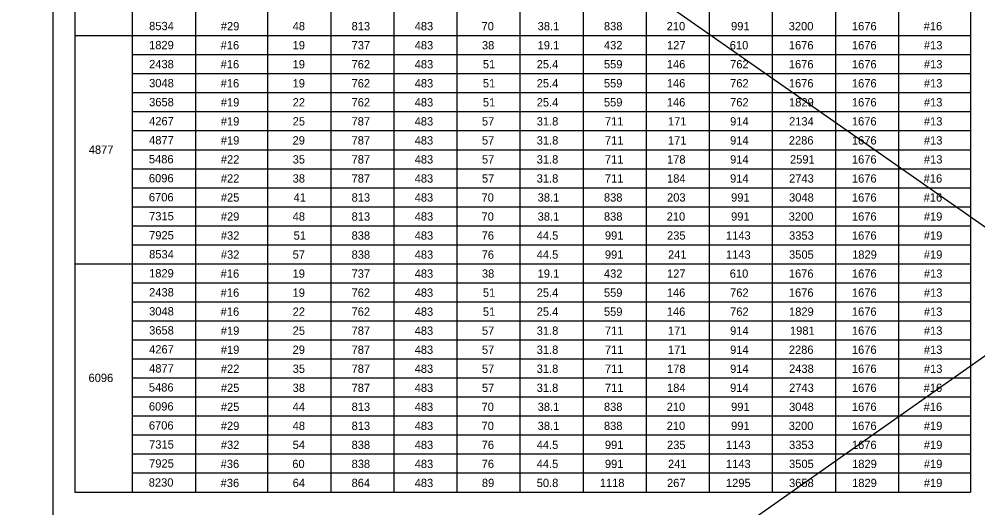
# Model space of a CAD drawing. Extents: x 3351 to 8430, y -3586 to 1457.
# Drawn here: x 7152.8 to 7507.3, y -991.4 to -810.5 of the extents above; entities that cross this region are included whole.
import ezdxf

# ---------------------------------------------------------------- set-up
doc = ezdxf.new("R2010")
doc.units = 0
doc.layers.add('1', color=7, linetype='Continuous')
doc.layers.add('2', color=7, linetype='Continuous')

msp = doc.modelspace()

# ---------------------------------------------------------------- linework, layer by layer
at = {"layer": '1'}
for p, q in [((7152.8, -637.24), (7925.95, -1178.57)), ((7927.1, -641.21), (7154.13, -1185.98)), ((7173.34, -639.31), (7173.34, -985.5)), ((7504.68, -639.31), (7504.68, -985.5)), ((7244.68, -703.31), (7244.68, -985.5)), ((7338.01, -703.31), (7338.01, -985.5)), ((7408.01, -703.31), (7408.01, -985.5)), ((7194.68, -985.5), (7194.68, -711.31)), ((7218.01, -711.31), (7218.01, -985.5)), ((7268.01, -711.31), (7268.01, -985.5)), ((7291.34, -711.31), (7291.34, -985.5)), ((7314.68, -711.31), (7314.68, -985.5)), ((7361.34, -711.31), (7361.34, -985.5)), ((7384.68, -711.31), (7384.68, -985.5)), ((7431.34, -711.31), (7431.34, -985.5)), ((7454.68, -711.31), (7454.68, -985.5)), ((7478.01, -711.31), (7478.01, -985.5)), ((7173.34, -816.54), (7504.68, -816.54)), ((7173.34, -816.54), (7504.68, -816.54)), ((7194.68, -823.58), (7504.68, -823.58)), ((7194.68, -830.62), (7504.68, -830.62)), ((7194.68, -837.66), (7504.68, -837.66)), ((7194.68, -844.7), (7504.68, -844.7)), ((7194.68, -851.74), (7504.68, -851.74)), ((7194.68, -858.78), (7504.68, -858.78)), ((7194.68, -865.82), (7504.68, -865.82)), ((7194.68, -872.86), (7504.68, -872.86)), ((7194.68, -879.9), (7504.68, -879.9)), ((7194.68, -886.94), (7504.68, -886.94)), ((7194.68, -893.98), (7504.68, -893.98)), ((7173.34, -901.02), (7504.68, -901.02)), ((7194.68, -908.06), (7504.68, -908.06)), ((7194.68, -915.1), (7504.68, -915.1)), ((7194.68, -922.14), (7504.68, -922.14)), ((7194.68, -929.18), (7504.68, -929.18)), ((7194.68, -936.22), (7504.68, -936.22)), ((7194.68, -943.26), (7504.68, -943.26)), ((7194.68, -950.3), (7504.68, -950.3)), ((7194.68, -957.34), (7504.68, -957.34)), ((7194.68, -964.38), (7504.68, -964.38)), ((7194.68, -971.42), (7504.68, -971.42)), ((7194.68, -978.46), (7504.68, -978.46)), ((7173.34, -985.5), (7504.68, -985.5))]:
    msp.add_line(p, q, dxfattribs=at)
at = {"layer": '2'}
msp.add_line((7165.34, -1195.31), (7165.34, -631.31), dxfattribs=at)

# ---------------------------------------------------------------- texts
at = {"layer": '1'}
for s, p in [('8534', (7200.86, -814.55)), ('#29', (7227.38, -814.6)), ('48', (7253.94, -814.6)), ('813', (7275.73, -814.6)), ('483', (7299.07, -814.6)), ('70', (7323.8, -814.6)), ('38.1', (7344.55, -814.6)), ('838', (7369.07, -814.6)), ('210', (7392.27, -814.6)), ('991', (7416.09, -814.6)), ('3200', (7437.4, -814.6)), ('1676', (7460.78, -814.6)), ('#16', (7487.31, -814.6)), ('1829', (7200.84, -821.59)), ('#16', (7227.31, -821.65)), ('19', (7253.92, -821.65)), ('737', (7275.73, -821.65)), ('483', (7299.07, -821.65)), ('38', (7323.94, -821.65)), ('19.1', (7344.55, -821.65)), ('432', (7369.07, -821.65)), ('127', (7392.4, -821.65)), ('610', (7415.6, -821.65)), ('1676', (7437.45, -821.65)), ('1676', (7460.78, -821.65)), ('#13', (7487.39, -821.65)), ('2438', (7200.86, -828.63)), ('#16', (7227.31, -828.69)), ('19', (7253.92, -828.69)), ('762', (7275.73, -828.69)), ('483', (7299.07, -828.69)), ('51', (7324.29, -828.69)), ('25.4', (7344.2, -828.69)), ('559', (7369.06, -828.69)), ('146', (7392.32, -828.69)), ('762', (7415.73, -828.69)), ('1676', (7437.45, -828.69)), ('1676', (7460.78, -828.69)), ('#13', (7487.39, -828.69)), ('3048', (7200.86, -835.67)), ('#16', (7227.31, -835.74)), ('19', (7253.92, -835.74)), ('762', (7275.73, -835.74)), ('483', (7299.07, -835.74)), ('51', (7324.29, -835.74)), ('25.4', (7344.2, -835.74)), ('559', (7369.06, -835.74)), ('146', (7392.32, -835.74)), ('762', (7415.73, -835.74)), ('1676', (7437.45, -835.74)), ('1676', (7460.78, -835.74)), ('#13', (7487.39, -835.74)), ('3658', (7200.86, -842.71)), ('#19', (7227.38, -842.78)), ('22', (7253.94, -842.78)), ('762', (7275.73, -842.78)), ('483', (7299.07, -842.78)), ('51', (7324.29, -842.78)), ('25.4', (7344.2, -842.78)), ('559', (7369.06, -842.78)), ('146', (7392.32, -842.78)), ('762', (7415.73, -842.78)), ('1829', (7437.52, -842.78)), ('1676', (7460.78, -842.78)), ('#13', (7487.39, -842.78)), ('4267', (7200.86, -849.75)), ('#19', (7227.38, -849.83)), ('25', (7253.94, -849.83)), ('787', (7275.73, -849.83)), ('483', (7299.07, -849.83)), ('57', (7323.94, -849.83)), ('31.8', (7344.2, -849.83)), ('711', (7369.42, -849.83)), ('171', (7392.75, -849.83)), ('914', (7415.73, -849.83)), ('2134', (7437.53, -849.83)), ('1676', (7460.78, -849.83)), ('#13', (7487.39, -849.83)), ('4877', (7200.86, -856.79)), ('#19', (7227.38, -856.87)), ('29', (7253.92, -856.87)), ('787', (7275.73, -856.87)), ('483', (7299.07, -856.87)), ('57', (7323.94, -856.87)), ('31.8', (7344.2, -856.87)), ('711', (7369.42, -856.87)), ('171', (7392.75, -856.87)), ('914', (7415.73, -856.87)), ('2286', (7437.45, -856.87)), ('1676', (7460.78, -856.87)), ('#13', (7487.39, -856.87)), ('4877', (7178.53, -860.31)), ('5486', (7200.77, -863.83)), ('#22', (7227.39, -863.91)), ('35', (7253.94, -863.91)), ('787', (7275.73, -863.91)), ('483', (7299.07, -863.91)), ('57', (7323.94, -863.91)), ('31.8', (7344.2, -863.91)), ('711', (7369.42, -863.91)), ('178', (7392.4, -863.91)), ('914', (7415.73, -863.91)), ('2591', (7437.88, -863.91)), ('1676', (7460.78, -863.91)), ('#13', (7487.39, -863.91)), ('6096', (7200.77, -870.87)), ('#22', (7227.39, -870.96)), ('38', (7253.94, -870.96)), ('787', (7275.73, -870.96)), ('483', (7299.07, -870.96)), ('57', (7323.94, -870.96)), ('31.8', (7344.2, -870.96)), ('711', (7369.42, -870.96)), ('184', (7392.4, -870.96)), ('914', (7415.73, -870.96)), ('2743', (7437.53, -870.96)), ('1676', (7460.78, -870.96)), ('#16', (7487.31, -870.96)), ('6706', (7200.77, -877.91)), ('#25', (7227.39, -878)), ('41', (7254.29, -878)), ('813', (7275.73, -878)), ('483', (7299.07, -878)), ('70', (7323.8, -878)), ('38.1', (7344.55, -878)), ('838', (7369.07, -878)), ('203', (7392.4, -878)), ('991', (7416.09, -878)), ('3048', (7437.53, -878)), ('1676', (7460.78, -878)), ('#16', (7487.31, -878)), ('7315', (7200.86, -884.95)), ('#29', (7227.38, -885.05)), ('48', (7253.94, -885.05)), ('813', (7275.73, -885.05)), ('483', (7299.07, -885.05)), ('70', (7323.8, -885.05)), ('38.1', (7344.55, -885.05)), ('838', (7369.07, -885.05)), ('210', (7392.27, -885.05)), ('991', (7416.09, -885.05)), ('3200', (7437.4, -885.05)), ('1676', (7460.78, -885.05)), ('#19', (7487.38, -885.05)), ('7925', (7200.86, -891.99)), ('#32', (7227.39, -892.09)), ('51', (7254.29, -892.09)), ('838', (7275.73, -892.09)), ('483', (7299.07, -892.09)), ('76', (7323.85, -892.09)), ('44.5', (7344.2, -892.09)), ('991', (7369.42, -892.09)), ('235', (7392.4, -892.09)), ('1143', (7414.2, -892.09)), ('3353', (7437.53, -892.09)), ('1676', (7460.78, -892.09)), ('#19', (7487.38, -892.09)), ('8534', (7200.86, -899.03)), ('#32', (7227.39, -899.14)), ('57', (7253.94, -899.14)), ('838', (7275.73, -899.14)), ('483', (7299.07, -899.14)), ('76', (7323.85, -899.14)), ('44.5', (7344.2, -899.14)), ('991', (7369.42, -899.14)), ('241', (7392.75, -899.14)), ('1143', (7414.2, -899.14)), ('3505', (7437.53, -899.14)), ('1829', (7460.85, -899.14)), ('#19', (7487.38, -899.14)), ('1829', (7200.84, -906.07)), ('#16', (7227.31, -906.18)), ('19', (7253.92, -906.18)), ('737', (7275.73, -906.18)), ('483', (7299.07, -906.18)), ('38', (7323.94, -906.18)), ('19.1', (7344.55, -906.18)), ('432', (7369.07, -906.18)), ('127', (7392.4, -906.18)), ('610', (7415.6, -906.18)), ('1676', (7437.45, -906.18)), ('1676', (7460.78, -906.18)), ('#13', (7487.39, -906.18)), ('2438', (7200.86, -913.11)), ('#16', (7227.31, -913.23)), ('19', (7253.92, -913.23)), ('762', (7275.73, -913.23)), ('483', (7299.07, -913.23)), ('51', (7324.29, -913.23)), ('25.4', (7344.2, -913.23)), ('559', (7369.06, -913.23)), ('146', (7392.32, -913.23)), ('762', (7415.73, -913.23)), ('1676', (7437.45, -913.23)), ('1676', (7460.78, -913.23)), ('#13', (7487.39, -913.23)), ('3048', (7200.86, -920.15)), ('#16', (7227.31, -920.27)), ('22', (7253.94, -920.27)), ('762', (7275.73, -920.27)), ('483', (7299.07, -920.27)), ('51', (7324.29, -920.27)), ('25.4', (7344.2, -920.27)), ('559', (7369.06, -920.27)), ('146', (7392.32, -920.27)), ('762', (7415.73, -920.27)), ('1829', (7437.52, -920.27)), ('1676', (7460.78, -920.27)), ('#13', (7487.39, -920.27)), ('3658', (7200.86, -927.19)), ('#19', (7227.38, -927.31)), ('25', (7253.94, -927.31)), ('787', (7275.73, -927.31)), ('483', (7299.07, -927.31)), ('57', (7323.94, -927.31)), ('31.8', (7344.2, -927.31)), ('711', (7369.42, -927.31)), ('171', (7392.75, -927.31)), ('914', (7415.73, -927.31)), ('1981', (7437.88, -927.31)), ('1676', (7460.78, -927.31)), ('#13', (7487.39, -927.31)), ('4267', (7200.86, -934.23)), ('#19', (7227.38, -934.36)), ('29', (7253.92, -934.36)), ('787', (7275.73, -934.36)), ('483', (7299.07, -934.36)), ('57', (7323.94, -934.36)), ('31.8', (7344.2, -934.36)), ('711', (7369.42, -934.36)), ('171', (7392.75, -934.36)), ('914', (7415.73, -934.36)), ('2286', (7437.45, -934.36)), ('1676', (7460.78, -934.36)), ('#13', (7487.39, -934.36)), ('4877', (7200.86, -941.27)), ('#22', (7227.39, -941.4)), ('35', (7253.94, -941.4)), ('787', (7275.73, -941.4)), ('483', (7299.07, -941.4)), ('57', (7323.94, -941.4)), ('31.8', (7344.2, -941.4)), ('711', (7369.42, -941.4)), ('178', (7392.4, -941.4)), ('914', (7415.73, -941.4)), ('2438', (7437.53, -941.4)), ('1676', (7460.78, -941.4)), ('#13', (7487.39, -941.4)), ('6096', (7178.45, -944.79)), ('5486', (7200.77, -948.31)), ('#25', (7227.39, -948.45)), ('38', (7253.94, -948.45)), ('787', (7275.73, -948.45)), ('483', (7299.07, -948.45)), ('57', (7323.94, -948.45)), ('31.8', (7344.2, -948.45)), ('711', (7369.42, -948.45)), ('184', (7392.4, -948.45)), ('914', (7415.73, -948.45)), ('2743', (7437.53, -948.45)), ('1676', (7460.78, -948.45)), ('#16', (7487.31, -948.45)), ('6096', (7200.77, -955.35)), ('#25', (7227.39, -955.49)), ('44', (7253.94, -955.49)), ('813', (7275.73, -955.49)), ('483', (7299.07, -955.49)), ('70', (7323.8, -955.49)), ('38.1', (7344.55, -955.49)), ('838', (7369.07, -955.49)), ('210', (7392.27, -955.49)), ('991', (7416.09, -955.49)), ('3048', (7437.53, -955.49)), ('1676', (7460.78, -955.49)), ('#16', (7487.31, -955.49)), ('6706', (7200.77, -962.39)), ('#29', (7227.38, -962.54)), ('48', (7253.94, -962.54)), ('813', (7275.73, -962.54)), ('483', (7299.07, -962.54)), ('70', (7323.8, -962.54)), ('38.1', (7344.55, -962.54)), ('838', (7369.07, -962.54)), ('210', (7392.27, -962.54)), ('991', (7416.09, -962.54)), ('3200', (7437.4, -962.54)), ('1676', (7460.78, -962.54)), ('#19', (7487.38, -962.54)), ('7315', (7200.86, -969.43)), ('#32', (7227.39, -969.58)), ('54', (7253.94, -969.58)), ('838', (7275.73, -969.58)), ('483', (7299.07, -969.58)), ('76', (7323.85, -969.58)), ('44.5', (7344.2, -969.58)), ('991', (7369.42, -969.58)), ('235', (7392.4, -969.58)), ('1143', (7414.2, -969.58)), ('3353', (7437.53, -969.58)), ('1676', (7460.78, -969.58)), ('#19', (7487.38, -969.58)), ('7925', (7200.86, -976.47)), ('#36', (7227.31, -976.63)), ('60', (7253.8, -976.63)), ('838', (7275.73, -976.63)), ('483', (7299.07, -976.63)), ('76', (7323.85, -976.63)), ('44.5', (7344.2, -976.63)), ('991', (7369.42, -976.63)), ('241', (7392.75, -976.63)), ('1143', (7414.2, -976.63)), ('3505', (7437.53, -976.63)), ('1829', (7460.85, -976.63)), ('#19', (7487.38, -976.63)), ('8230', (7200.72, -983.51)), ('#36', (7227.31, -983.67)), ('64', (7253.94, -983.67)), ('864', (7275.73, -983.67)), ('483', (7299.07, -983.67)), ('89', (7323.92, -983.67)), ('50.8', (7344.2, -983.67)), ('1118', (7367.53, -983.67)), ('267', (7392.4, -983.67)), ('1295', (7414.2, -983.67)), ('3658', (7437.53, -983.67)), ('1829', (7460.85, -983.67)), ('#19', (7487.38, -983.67))]:
    msp.add_text(s, height=3.07, dxfattribs=at).set_placement(p)

doc.saveas('drawing.dxf')
